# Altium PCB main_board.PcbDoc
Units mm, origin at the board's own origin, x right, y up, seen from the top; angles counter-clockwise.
Board outline 80.25 x 51.3 mm, 2 copper layers (Top Layer, Bottom Layer); 11 components, 14 nets, 55 pads, 122 vias.
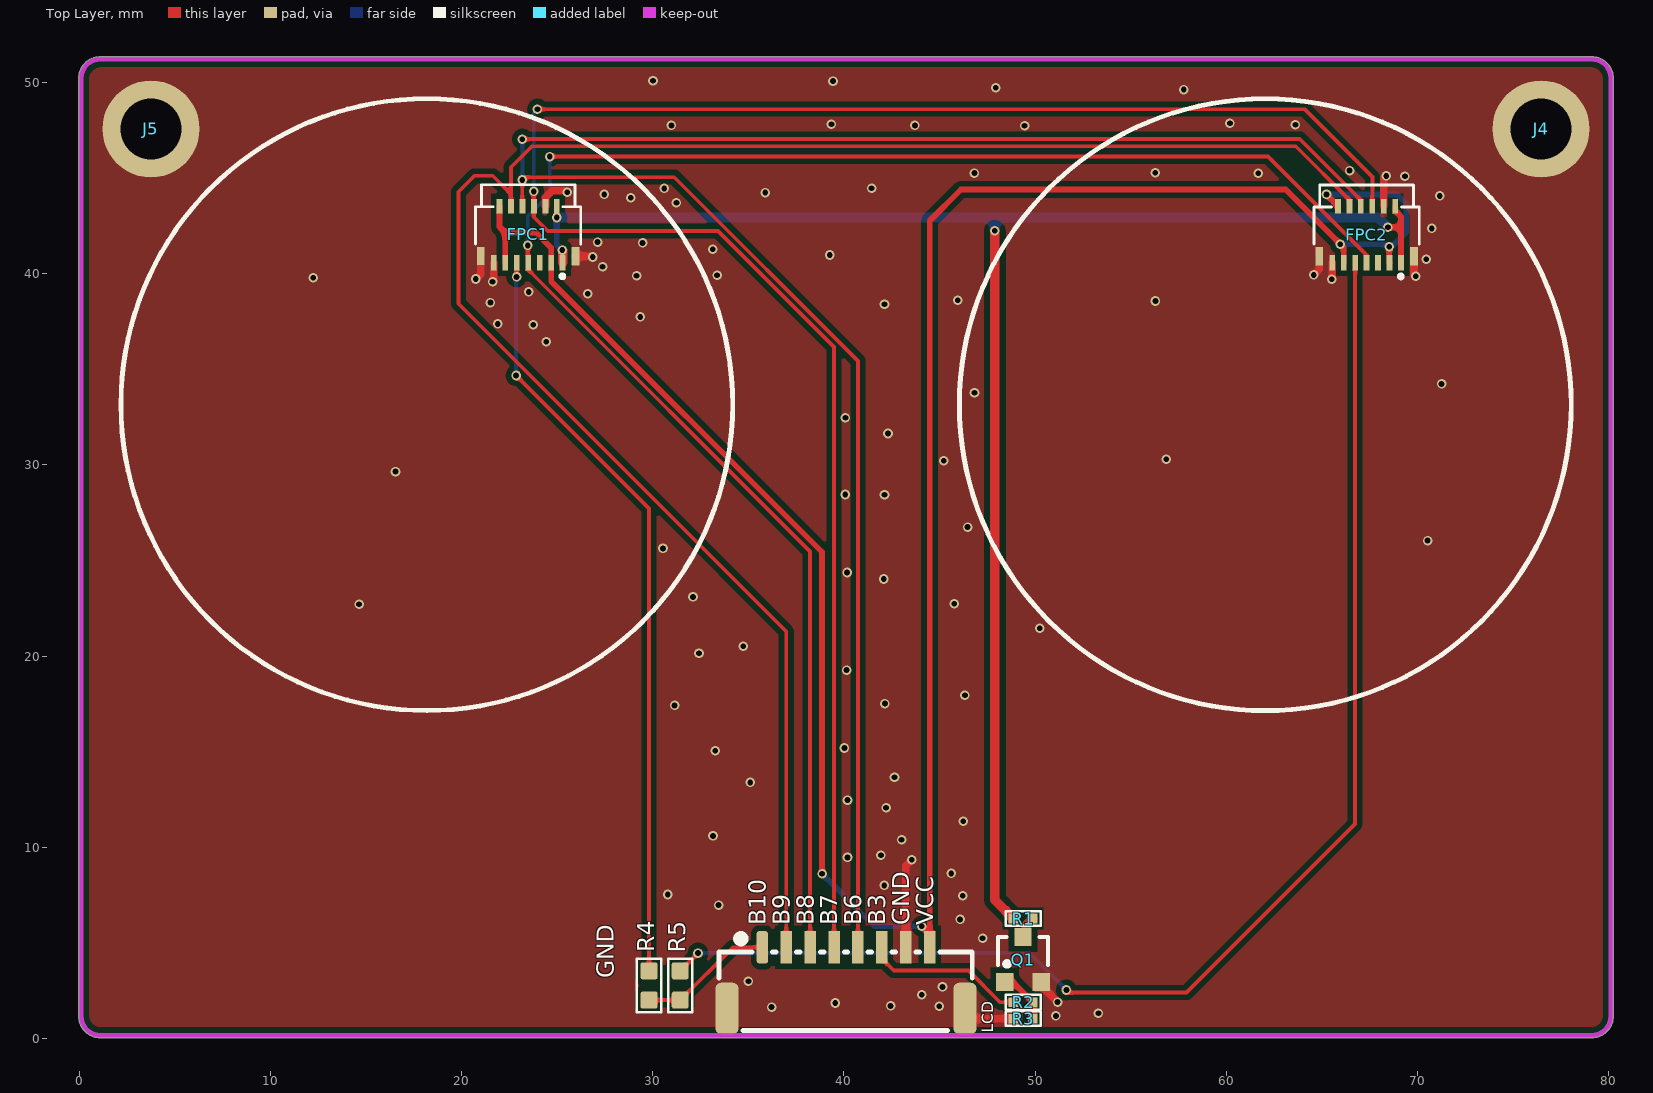
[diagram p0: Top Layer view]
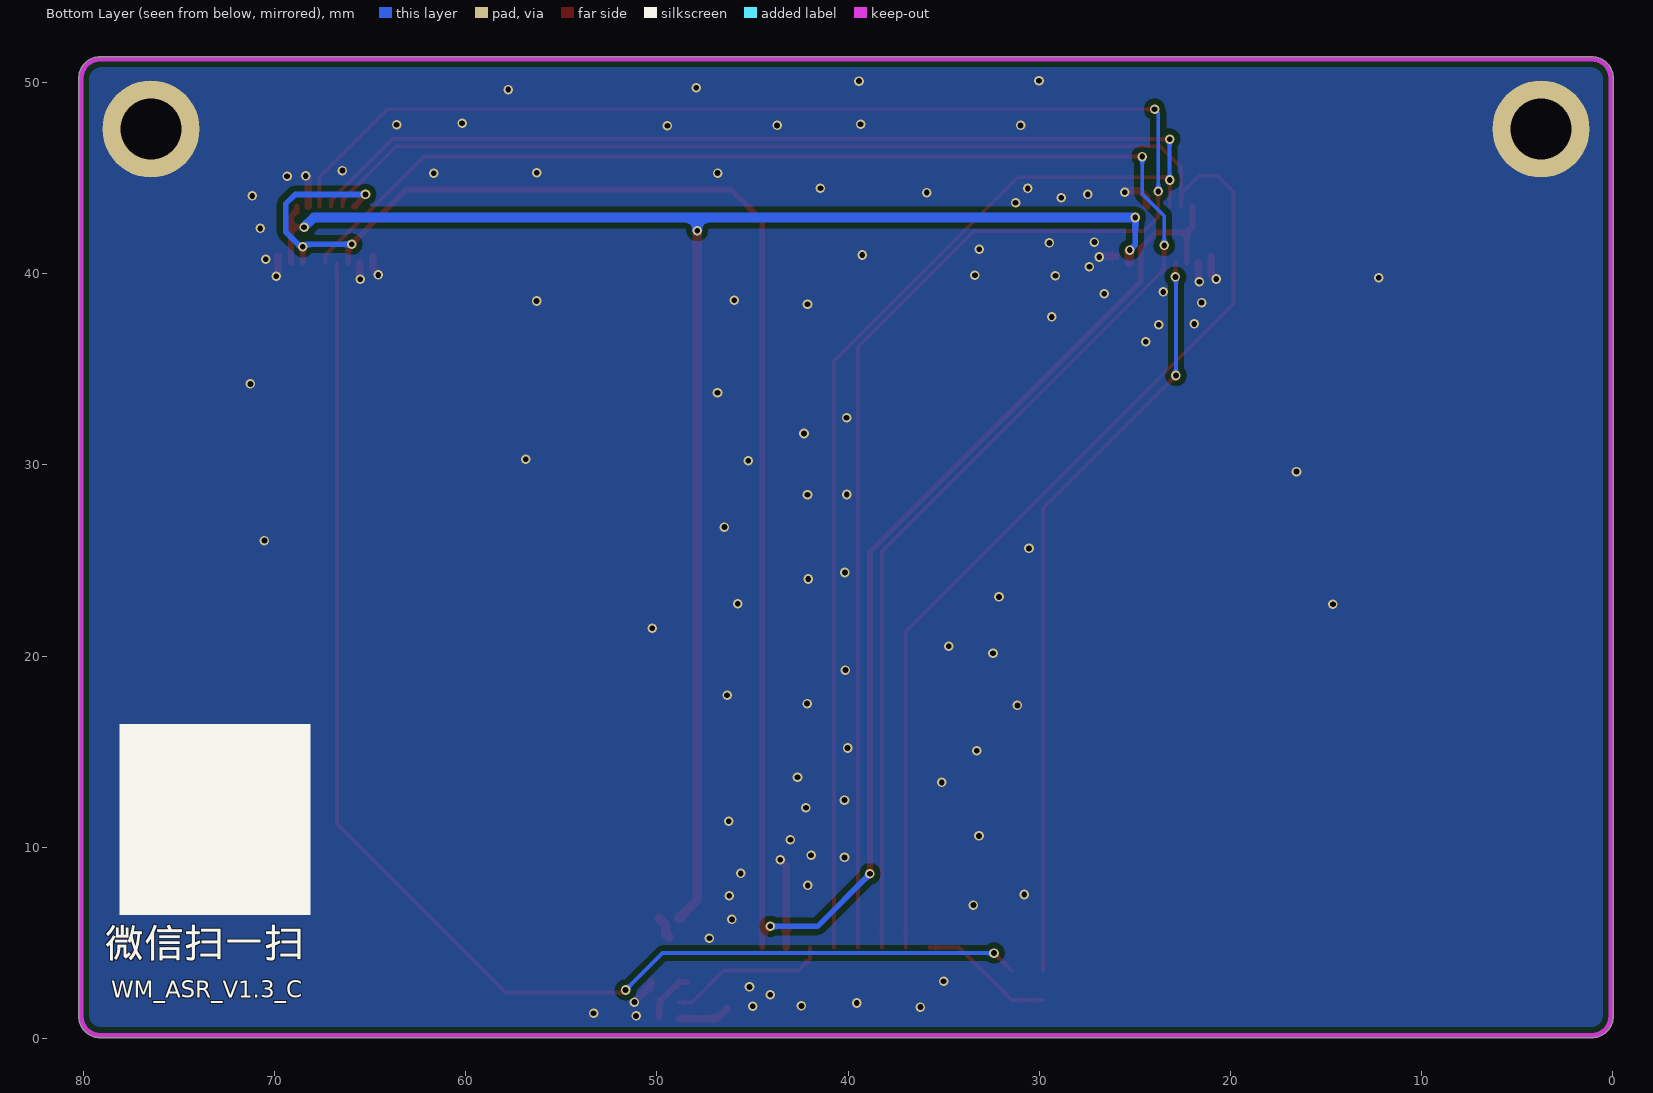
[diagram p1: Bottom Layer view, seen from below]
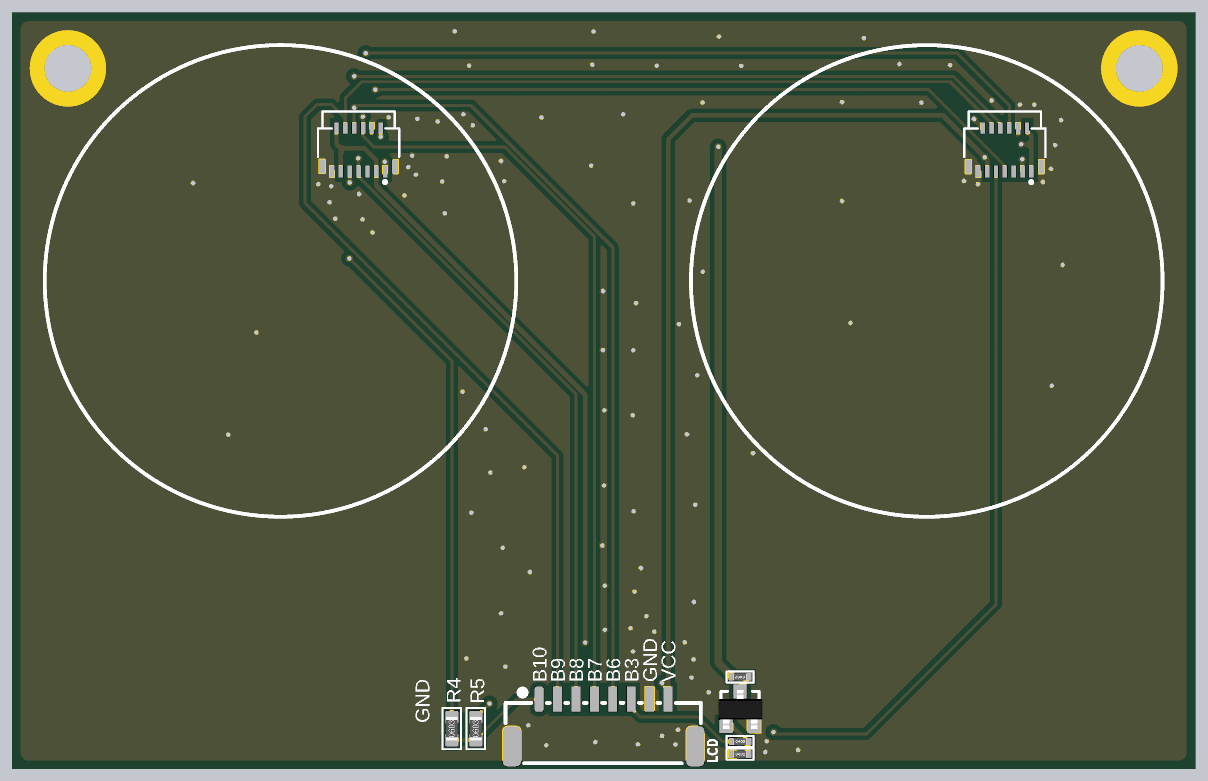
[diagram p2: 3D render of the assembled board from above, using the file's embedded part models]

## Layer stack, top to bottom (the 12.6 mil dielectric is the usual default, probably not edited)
Top Solder: solder mask 0.0102, Solder Resist, Dk 3.5
Top Layer: signal copper 0.0356
Dielectric 1: dielectric 0.32, FR-4, Dk 4.8
Bottom Layer: signal copper 0.0356
Bottom Solder: solder mask 0.0102, Solder Resist, Dk 3.5

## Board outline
-0.016,1.172 -0.016,50.222 cw(c1.111,50.222) 1.027,51.346 cw(c1.055,51.222) 1.055,51.349 79.111,51.349 cw(c79.111,50.222) 80.238,50.222 cw(c80.111,50.222) 80.236,50.196 cw(c80.111,50.169) 80.238,50.169 80.238,1.172 cw(c79.111,1.172) 79.111,0.045 1.111,0.045 cw(c1.111,1.172)

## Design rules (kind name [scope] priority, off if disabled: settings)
Clearance Clearance_freep_ad [HasPad('Free-6') Or HasPad('Free-7') Or HasPad('Free-8') or HasPad('Free-HOLE')] p1: gap=1
Clearance polygon [inpolygon] p2: gap=0.3
Clearance ic [HasFootprint('LQFP48_N') Or HasFootprint('HMC5883L')or HasFootprint('RP4')or HasFootprint('USBMICRO2') Or HasFootprint('JP2_SMD')] p3: gap=0.102
Clearance [All And Not IsKeepOut vs All And Not IsKeepOut] p4: gap=0.17
ComponentClearance [InComponent('J1') vs InComponent('SW1')] p1 off: gap=0 collisioncheckmode=3 verticalgap=2540 showdistances=FALSE
DiffPairsRouting [All] p1: maxlimit=0.254 minlimit=0.2 mostfreqgap=0.2 toplayer_minwidth=0.381 toplayer_maxwidth=0.381 toplayer_prefwidth=0.381 bottomlayer_minwidth=0.381 bottomlayer_maxwidth=0.381 bottomlayer_prefwidth=0.381 maxuncoupledlength=12.7
FabricationTestpoint [(IsPad And (OnTopLayer Or OnBottomLayer))] p1: side=3 testpointundercomponent=TRUE minsize=1.016 maxsize=2.54 preferedsize=1.524 minholesize=0 maxholesize=1.016 preferedholesize=0.813 testpointgrid=0.025 allowsidetop=TRUE allowsidebottom=TRUE usegrid=TRUE gridtolerance=0
HoleSize [All] p1: absolutevalues=TRUE maxlimit=5.08 minlimit=0.152 maxpercent=80.000 minpercent=20.000
MinimumSolderMaskSliver [All] p1: minsoldermaskwidth=0.025
PolygonConnect PolygonConnect_1 [isvia] p1: connectstyle=Direct reliefconductorwidth=0.254 reliefentries=4 polygonreliefangle="90 Angle" airgapwidth=0.254
PolygonConnect [All] p2: connectstyle=Direct reliefconductorwidth=0.254 reliefentries=4 polygonreliefangle="90 Angle" airgapwidth=0.254
RoutingVias [All] p1: holewidth=0.35 width=0.7 viastyle="Through Hole" minholewidth=0.3 minwidth=0.35 maxholewidth=10 maxwidth=10
ShortCircuit [InNet('ANT1') vs InNet('GND')] p1: allowed=TRUE
SilkToSilkClearance [All] p1: silktosilkclearance=0
SilkToSolderMaskClearance SilkscreenOverComponentPads [IsPad] p1 off: minsilkscreentomaskgap=0.051 clearancetoexposedcopper=TRUE
SolderMaskExpansion [All] p1: expansion=0.051
Width Width_1 [InNet('VCC')] p1: maxlimit=25.4 minlimit=0.178 preferedwidth=0.635
Width [All] p2: maxlimit=10 minlimit=0.2 preferedwidth=0.254
22 further rules are at their usual default settings.

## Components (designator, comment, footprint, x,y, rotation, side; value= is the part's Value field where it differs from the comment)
FPC1 "FH35C-13S-0.3SHW(50)" FPC-SMD_13P-P0.60_HRS_FH35C-13S-0.3SHW 23.489,42.054 r0 top locked
FPC2 "FH35C-13S-0.3SHW(50)" FPC-SMD_13P-P0.60_HRS_FH35C-13S-0.3SHW 67.339,42.049 r0 top locked
J4 "M3" "M3 125X200" 76.463,47.573 r0 top
J5 "M3" "M3 125X200" 3.763,47.573 r0 top
LCD "Header_10" CONN-SMD_SM08B-GHS-TB-LF-SN 40.111,3.171 r0 top
Q1 "S8050" SOT-23-3 49.368,4.133 r0 top
R1 "0R" R0402 49.375,6.279 r180 top
R2 "1K" R0402 49.375,1.902 r0 top
R3 "4.7K" R0402 49.375,1.044 r0 top
R4 "0R" R0603 29.812,2.777 r90 top
R5 "0R" R0603 31.44,2.777 r90 top

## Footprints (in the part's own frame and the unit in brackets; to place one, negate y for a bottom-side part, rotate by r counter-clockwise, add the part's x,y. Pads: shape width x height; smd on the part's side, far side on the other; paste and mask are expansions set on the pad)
CONN-SMD_SM08B-GHS-TB-LF-SN [mm]
  rrect50% 0.6x1.7 smd paste+0 mask+0.05: 1(-4.375,1.6)
  rect 0.6x1.7 smd paste+0 mask+0.05: 2(-3.125,1.6) 3(-1.875,1.6) 4(-0.625,1.6) 5(0.625,1.6) 6(1.875,1.6) 7(3.125,1.6) 8(4.375,1.6)
  rrect50% 1.21x2.7 smd paste+0 mask+0.05: 9(-6.225,-1.6) 10(6.225,-1.6)
  silkscreen extent -6.65,-2.75 6.6,2.25
FPC-SMD_13P-P0.60_HRS_FH35C-13S-0.3SHW [mm]
  rect 0.3x0.8 smd: 1(1.8,-1.473) 3(1.2,-1.473) 5(0.6,-1.473) 7(0,-1.473) 9(-0.6,-1.473) 11(-1.2,-1.473) 13(-1.8,-1.473)
  rect 0.3x0.75 smd: 2(1.5,1.473) 4(0.902,1.473) 6(0.3,1.473) 8(-0.3,1.473) 10(-0.9,1.473) 12(-1.5,1.473)
  rect 0.4x0.95 smd: 14(-2.479,-1.133) 15(2.479,-1.138)
  silkscreen extent -21.3,-24.9 10.7,7.1
"M3 125X200" [mm] "M3螺丝孔，孔125Mil，焊盘200Mil"
  round 5.08 hole 3.175: 1(0,0)
R0402 [mil]
  rect 20x20 smd: 1(-20,0) 2(20,0)
  silkscreen extent -36,-15 36,15, body extent -20,-10 20,10, height 20
R0603 [mil]
  rrect25% 35x35 smd: 1(-30,0) 2(30,0)
  silkscreen extent -55,-25 55,25, body extent -31,-16 32,16, height 18
SOT-23-3 [mm]
  rect 0.9x0.95 smd: 1(-0.95,-1.175) 2(0.95,-1.175) 3(0,1.175)
  silkscreen extent -1.3,-0.35 1.3,1.18, body extent -1.48,-1.37 1.52,1.27, height 1.08

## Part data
FPC1 FPC2: library part FH35C-13S-0.3SHW(50)_C2889266
J4 J5: "铜柱孔"
LCD: library part 180DIP_PH_10
R1: library part R0402/0R
R2: library part R0402/1K
R3: library part R0402/4.7K
R4 R5: library part R0603/0R

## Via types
v1: diameter 0.5, hole 0.3, Top Layer to Bottom Layer, tented both sides, 122 vias

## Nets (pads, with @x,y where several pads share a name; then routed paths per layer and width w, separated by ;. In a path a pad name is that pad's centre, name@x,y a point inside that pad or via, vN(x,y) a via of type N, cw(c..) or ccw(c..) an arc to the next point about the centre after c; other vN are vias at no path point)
3V3: FPC1.3 FPC1.11 FPC1.12 FPC2.3 FPC2.11 FPC2.12 LCD.8 | length 125.1
  Top Layer w0.3: FPC1.12 21.989,42.451 22.289,42.151 ; FPC1.11 22.289,42.151 ; v1(38.859,8.616) 38.859,25.442 24.689,39.612 FPC1.3 24.689,41.36 23.898,42.151 22.289,42.151 ; v1(44.07,5.868) LCD.8@44.486,5.452 ; LCD.8 LCD.8@44.486,5.452 ; v1(65.241,44.146) 65.241,44.12 FPC2.12 ; FPC2.11 66.139,41.374 v1(65.966,41.547) 63.113,44.4 46.118,44.4 44.486,42.768 LCD.8@44.486,5.452 ; v1(68.516,41.405) 68.516,40.6 FPC2.3
  Bottom Layer w0.3: v1(38.859,8.616) 41.607,5.868 v1(44.07,5.868) ; v1(65.241,44.146) 68.918,44.146 69.417,43.647 69.417,42.193 68.629,41.405 v1(68.516,41.405) 68.374,41.547 v1(65.966,41.547)
B3: LCD.6 R2.1 | length 8.4
  Top Layer w0.2: LCD.6 41.986,4.177 42.608,3.555 46.512,3.555 48.165,1.902 R2.1
B6: FPC1.8 FPC2.8 LCD.5 | length 101.3
  Top Layer w0.2: v1(23.186,47.039) 63.842,47.039 67.038,43.843 FPC2.8 ; FPC1.8 23.183,43.532 v1(23.183,44.903) 23.33,45.05 31.126,45.05 40.736,35.44 LCD.5
  Bottom Layer w0.2: v1(23.183,44.903) 23.111,44.975 23.186,45.05 v1(23.186,47.039)
B7: FPC1.6 FPC2.6 LCD.4 | length 102.3
  Top Layer w0.2: v1(23.779,44.303) 23.779,42.97 24.516,42.233 33.42,42.233 39.486,36.167 LCD.4 ; v1(23.973,48.607) 64.085,48.607 67.639,45.053 FPC2.6
  Bottom Layer w0.2: v1(23.779,44.303) 23.779,48.413 v1(23.973,48.607)
B8: FPC1.7 FPC2.7 LCD.3 | length 93.2
  Top Layer w0.2: v1(23.47,41.48) 23.47,40.237 38.236,25.471 LCD.3 ; v1(24.615,46.128) 62.184,46.128 67.339,40.973 FPC2.7
  Bottom Layer w0.2: v1(23.47,41.48) 23.47,43.026 24.615,44.171 v1(24.615,46.128)
B9: FPC1.10 FPC2.10 LCD.2 | length 97.9
  Top Layer w0.2: FPC1.10 22.589,44.167 ; LCD.2 36.986,21.298 19.85,38.434 19.85,44.286 20.685,45.121 21.635,45.121 22.589,44.167 ; FPC2.10 66.438,43.861 63.63,46.669 23.687,46.669 22.589,45.571 22.589,44.167
B10: LCD.1 R4.1 R5.1 | length 7.1
  Top Layer w0.2: R4.1 R5.1 34.196,4.771 LCD.1
CS1: FPC1.9 R4.2 | length 39.9
  Top Layer w0.2: v1(22.856,34.677) 29.812,27.721 R4.2 ; v1(22.884,39.834) 22.884,40.576 FPC1.9
  Bottom Layer w0.2: v1(22.856,34.677) 22.856,39.806 v1(22.884,39.834)
CS2: FPC2.9 R5.2 | length 69.6
  Top Layer w0.2: R5.2 v1(32.372,4.471) v1@32.372,4.488 ; v1(51.638,2.539) 51.775,2.402 57.917,2.402 66.739,11.224 FPC2.9
  Bottom Layer w0.2: v1(32.372,4.471) 49.706,4.471 v1(51.638,2.539)
GND: FPC1.4 FPC1.13 FPC1.14 FPC1.15 FPC2.4 FPC2.13 FPC2.14 FPC2.15 J4.1 J5.1 LCD.7 LCD.9 LCD.10 Q1.2 R3.1 | length 18.6
  Top Layer w0.4: v1(20.752,39.725) 21.01,39.983 FPC1.14 ; v1(21.629,39.582) 21.689,39.642 FPC1.13 ; FPC1.4 24.391,43.984 24.742,44.335 25.458,44.335 v1(25.531,44.262) ; FPC1.15 26.824,40.915 v1(26.863,40.876) ; LCD.7 43.236,9.043 v1(43.552,9.359) ; LCD.10 46.863,1.044 R3.1 ; Q1.2 50.318,2.771 v1(51.178,1.911) ; v1(64.571,39.938) 64.86,40.227 FPC2.14 ; v1(65.512,39.714) 65.539,39.741 FPC2.13 ; FPC2.4 68.241,44.993 v1(68.362,45.114) ; FPC2.15 69.817,39.957 v1(69.911,39.863)
  other v1: 51.088,1.185 53.311,1.327 36.219,1.648 42.442,1.706 44.986,1.697 39.549,1.862 44.078,2.289 45.159,2.701 35.006,2.998 47.252,5.24 46.078,6.232 33.449,6.983 46.217,7.472 30.794,7.536 42.107,8.009 45.611,8.639 40.189,9.474 41.938,9.588 43.019,10.405 33.154,10.596 46.239,11.367 42.209,12.069 40.189,12.472 35.108,13.398 42.646,13.672 33.268,15.054 40.029,15.197 31.144,17.425 42.146,17.522 46.329,17.959 40.143,19.271 32.424,20.151 34.739,20.513 50.25,21.461 14.644,22.718 45.768,22.745 32.109,23.1 42.084,24.035 40.166,24.376 30.539,25.635 70.527,26.044 46.469,26.752 40.068,28.455 42.124,28.447 16.55,29.653 45.222,30.221 56.86,30.302 42.307,31.646 40.079,32.47 46.831,33.78 71.257,34.236 24.435,36.437 23.755,37.33 21.898,37.374 29.345,37.741 42.124,38.41 21.514,38.492 56.293,38.575 45.95,38.608 26.6,38.952 23.525,39.051 12.251,39.792 29.159,39.9 33.368,39.923 27.378,40.366 70.464,40.755 39.265,40.98 33.145,41.286 29.471,41.61 27.12,41.654 70.748,42.369 31.241,43.714 28.857,43.972 71.162,44.068 27.471,44.147 35.893,44.246 30.6,44.46 41.45,44.469 69.343,45.104 46.828,45.263 61.671,45.253 56.287,45.285 66.447,45.396 30.983,47.758 43.717,47.758 49.451,47.744 63.614,47.796 39.347,47.817 60.19,47.867 57.772,49.631 47.939,49.734 30.016,50.092 39.43,50.078
LEDK: FPC1.1 FPC1.2 FPC2.1 FPC2.2 R1.2 | length 87
  Top Layer w0.3: v1(68.452,42.434) 68.461,42.425 69.139,42.425 ; FPC2.2 68.839,43.287 69.139,42.987 69.139,42.425 ; FPC2.1 69.139,42.425
  Top Layer w0.5: v1(25.266,41.239) 25.289,41.216 FPC1.1 ; v1(47.892,42.255) 47.892,7.254 R1.2
  Bottom Layer w0.3: v1(24.985,42.942) 24.985,41.52 v1(25.266,41.239)
  Bottom Layer w0.5: v1(24.985,42.942) 47.892,42.942 ; v1(47.892,42.255) 47.892,42.942 ; v1(68.452,42.434) 67.944,42.942 47.892,42.942
NetQ1_1: Q1.1 R2.2 R3.2 | length 2.8
  Top Layer w0.3: Q1.1 48.827,2.958 R2.2 R3.2
NetQ1_3: Q1.3 R1.1 | length 1.2
  Top Layer w0.5: Q1.3 49.541,5.481 49.541,5.937 R1.1
TE: FPC2.5
pads on no net: FPC1.5

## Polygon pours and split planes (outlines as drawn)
GND on Top Layer "Top Layer-No Net" (solid, remove dead copper, pour order 0): -7.858,56.381 86.242,56.381 86.242,-3.339 -7.761,-3.339
GND on Bottom Layer "Top Layer-No Net" (solid, remove dead copper, pour order 4): -8.645,57.049 85.455,57.049 85.455,-2.671 -8.548,-2.671

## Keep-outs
Keep-Out Layer:
  lines w0.254: 1.055,51.222 79.111,51.222 cw(c79.111,50.222) 80.111,50.222 ; 1.111,51.222 ccw(c1.111,50.222) 0.111,50.222 0.111,1.172 ccw(c1.111,1.172) 1.111,0.172 79.111,0.172 ccw(c79.111,1.172) 80.111,1.172 80.111,50.169

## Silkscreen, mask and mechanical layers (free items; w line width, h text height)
Top Overlay:
  text "B10" at 36.229,5.933 h1.52 r90
  text "B9" at 37.479,5.933 h1.52 r90
  text "B8" at 38.729,5.933 h1.52 r90
  text "B7" at 39.979,5.933 h1.52 r90
  text "B6" at 41.229,5.933 h1.52 r90
  text "B3" at 42.479,5.933 h1.52 r90
  text "GND" at 43.729,5.933 h1.52 r90
  text "VCC" at 44.979,5.933 h1.52 r90
  text "GND" at 28.284,3.165 h1.52 r90
Bottom Overlay:
  region: 68.117,16.464 68.117,6.464 78.117,6.464 78.117,16.464
  text "微信扫一扫" at 78.903,3.748 h2.6
  text "WM_ASR_V1.3_C" at 78.547,1.856 h1.5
